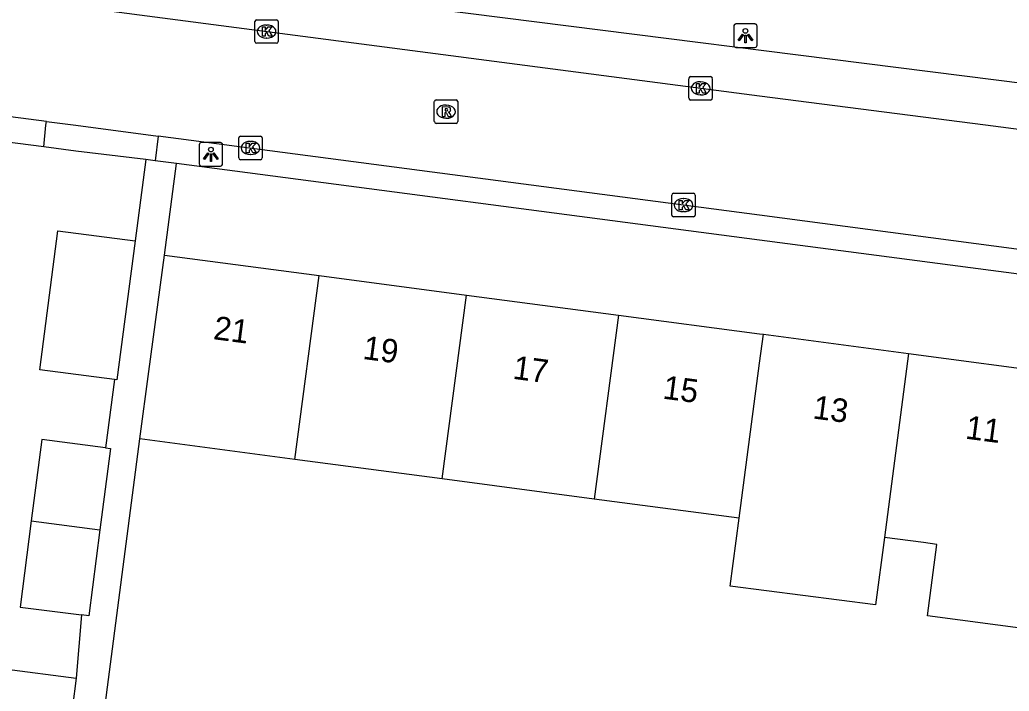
# Model space of a CAD drawing. Extents: x 162186 to 163152, y 385513 to 386513.
# Drawn here: x 162468.5 to 162510.63, y 386225.89 to 386254.5 of the extents above; entities that cross this region are included whole.
import ezdxf

# ---------------------------------------------------------------- set-up
doc = ezdxf.new("R2010")
doc.units = 0
for name, color, linetype in [('IMGEO_Kolk', 7, 'Continuous'), ('IMGEO_Lichtpunt', 7, 'Continuous'), ('IMGEO_Muur', 7, 'Continuous'), ('IMGEO_Pand', 7, 'Continuous'), ('IMGEO_Pand_nummerreeks', 7, 'Continuous'), ('IMGEO_Rijbaan_lokaal_open', 7, 'Continuous'), ('IMGEO_Rioolput', 7, 'Continuous'), ('IMGEO_Voetpad_open', 7, 'Continuous')]:
    doc.layers.add(name, color=color, linetype=linetype)

msp = doc.modelspace()

# ---------------------------------------------------------------- linework, layer by layer
at = {"layer": 'IMGEO_Kolk'}
for p, q in [((162478.506, 386253.568), (162478.506, 386254.42)), ((162478.581, 386254.494), (162479.433, 386254.494)), ((162479.507, 386254.42), (162479.507, 386253.568)), ((162478.994, 386254.274), (162479.019, 386254.274)), ((162479.433, 386253.494), (162478.581, 386253.494)), ((162479.017, 386253.714), (162478.992, 386253.714)), ((162496.989, 386251.15), (162496.989, 386252.002)), ((162497.064, 386252.076), (162497.916, 386252.076)), ((162497.477, 386251.856), (162497.502, 386251.856)), ((162497.99, 386252.002), (162497.99, 386251.15)), ((162497.916, 386251.076), (162497.064, 386251.076)), ((162497.5, 386251.296), (162497.475, 386251.296)), ((162477.822, 386248.609), (162477.822, 386249.461)), ((162477.897, 386249.535), (162478.749, 386249.535)), ((162478.31, 386249.315), (162478.335, 386249.315)), ((162478.823, 386249.461), (162478.823, 386248.609)), ((162478.749, 386248.535), (162477.897, 386248.535)), ((162478.333, 386248.755), (162478.308, 386248.755)), ((162496.263, 386246.177), (162496.263, 386247.029)), ((162496.338, 386247.103), (162497.19, 386247.103)), ((162496.751, 386246.883), (162496.776, 386246.883)), ((162497.264, 386247.029), (162497.264, 386246.177)), ((162496.774, 386246.323), (162496.749, 386246.323)), ((162497.19, 386246.103), (162496.338, 386246.103))]:
    msp.add_line(p, q, dxfattribs=at)
for points in [[(162478.506, 386253.568), (162478.506, 386254.42)], [(162478.581, 386254.494), (162479.433, 386254.494)], [(162479.507, 386254.42), (162479.507, 386253.568)], [(162478.827, 386254.194), (162478.95, 386254.194), (162478.95, 386254.043), (162479.08, 386254.194), (162479.244, 386254.194), (162479.098, 386254.043), (162479.251, 386253.794), (162479.099, 386253.794), (162479.014, 386253.958), (162478.95, 386253.891), (162478.95, 386253.794), (162478.827, 386253.794), (162478.827, 386254.194)], [(162479.433, 386253.494), (162478.581, 386253.494)], [(162496.989, 386251.15), (162496.989, 386252.002)], [(162497.064, 386252.076), (162497.916, 386252.076)], [(162497.99, 386252.002), (162497.99, 386251.15)], [(162497.31, 386251.776), (162497.433, 386251.776), (162497.433, 386251.625), (162497.563, 386251.776), (162497.727, 386251.776), (162497.581, 386251.625), (162497.734, 386251.376), (162497.582, 386251.376), (162497.497, 386251.54), (162497.433, 386251.473), (162497.433, 386251.376), (162497.31, 386251.376), (162497.31, 386251.776)], [(162497.916, 386251.076), (162497.064, 386251.076)], [(162477.822, 386248.609), (162477.822, 386249.461)], [(162477.897, 386249.535), (162478.749, 386249.535)], [(162478.823, 386249.461), (162478.823, 386248.609)], [(162478.143, 386249.235), (162478.266, 386249.235), (162478.266, 386249.084), (162478.396, 386249.235), (162478.56, 386249.235), (162478.414, 386249.084), (162478.567, 386248.835), (162478.415, 386248.835), (162478.33, 386248.999), (162478.266, 386248.932), (162478.266, 386248.835), (162478.143, 386248.835), (162478.143, 386249.235)], [(162478.749, 386248.535), (162477.897, 386248.535)], [(162496.263, 386246.177), (162496.263, 386247.029)], [(162496.338, 386247.103), (162497.19, 386247.103)], [(162496.584, 386246.803), (162496.707, 386246.803), (162496.707, 386246.652), (162496.837, 386246.803), (162497.001, 386246.803), (162496.855, 386246.652), (162497.008, 386246.403), (162496.856, 386246.403), (162496.771, 386246.567), (162496.707, 386246.5), (162496.707, 386246.403), (162496.584, 386246.403), (162496.584, 386246.803)], [(162497.264, 386247.029), (162497.264, 386246.177)], [(162497.19, 386246.103), (162496.338, 386246.103)]]:
    msp.add_lwpolyline(points, dxfattribs=at)
for centre, start, end in [((162478.583, 386254.418), 91.552, 178.448), ((162478.583, 386254.418), 91.552, 178.448), ((162479.431, 386254.418), 1.552, 88.448), ((162479.431, 386254.418), 1.552, 88.448), ((162478.583, 386253.57), 181.552, 268.448), ((162478.583, 386253.57), 181.552, 268.448), ((162479.431, 386253.57), 271.552, 358.448), ((162479.431, 386253.57), 271.552, 358.448), ((162497.066, 386252), 91.552, 178.448), ((162497.066, 386252), 91.552, 178.448), ((162497.914, 386252), 1.552, 88.448), ((162497.914, 386252), 1.552, 88.448), ((162497.066, 386251.152), 181.552, 268.448), ((162497.066, 386251.152), 181.552, 268.448), ((162497.914, 386251.152), 271.552, 358.448), ((162497.914, 386251.152), 271.552, 358.448), ((162477.899, 386249.459), 91.552, 178.448), ((162477.899, 386249.459), 91.552, 178.448), ((162478.747, 386249.459), 1.552, 88.448), ((162478.747, 386249.459), 1.552, 88.448), ((162477.899, 386248.611), 181.552, 268.448), ((162477.899, 386248.611), 181.552, 268.448), ((162478.747, 386248.611), 271.552, 358.448), ((162478.747, 386248.611), 271.552, 358.448), ((162496.34, 386247.027), 91.552, 178.448), ((162496.34, 386247.027), 91.552, 178.448), ((162497.188, 386247.027), 1.552, 88.448), ((162497.188, 386247.027), 1.552, 88.448), ((162496.34, 386246.179), 181.552, 268.448), ((162496.34, 386246.179), 181.552, 268.448), ((162497.188, 386246.179), 271.552, 358.448), ((162497.188, 386246.179), 271.552, 358.448)]:
    msp.add_arc(centre, 0.0765, start, end, dxfattribs=at)
for centre, major_axis, ratio, start_param, end_param in [((162478.993, 386253.994), (-0.387, 0.002), 0.722429, 4.712389, 7.853982), ((162479.018, 386253.994), (-0.39, 0.002), 0.717154, 1.570796, 4.712389), ((162497.476, 386251.576), (-0.387, 0.002), 0.722429, 4.712389, 7.853982), ((162497.501, 386251.576), (-0.39, 0.002), 0.717154, 1.570796, 4.712389), ((162478.309, 386249.035), (-0.387, 0.002), 0.722429, 4.712389, 7.853982), ((162478.334, 386249.035), (-0.39, 0.002), 0.717154, 1.570796, 4.712389), ((162496.75, 386246.603), (-0.387, 0.002), 0.722429, 4.712389, 7.853982), ((162496.775, 386246.603), (-0.39, 0.002), 0.717154, 1.570796, 4.712389)]:
    msp.add_ellipse(centre, major_axis=major_axis, ratio=ratio, start_param=start_param, end_param=end_param, dxfattribs=at)
at = {"layer": 'IMGEO_Lichtpunt'}
for p, q in [((162499.803, 386254.317), (162498.995, 386254.317)), ((162499.803, 386254.317), (162498.995, 386254.317)), ((162498.901, 386254.222), (162498.901, 386253.415)), ((162498.901, 386254.222), (162498.901, 386253.415)), ((162499.897, 386253.415), (162499.897, 386254.222)), ((162499.897, 386253.415), (162499.897, 386254.222)), ((162498.995, 386253.321), (162499.803, 386253.321)), ((162498.995, 386253.321), (162499.803, 386253.321)), ((162477.04, 386249.263), (162476.232, 386249.263)), ((162477.04, 386249.263), (162476.232, 386249.263)), ((162476.138, 386249.168), (162476.138, 386248.361)), ((162476.138, 386249.168), (162476.138, 386248.361)), ((162477.134, 386248.361), (162477.134, 386249.168)), ((162477.134, 386248.361), (162477.134, 386249.168)), ((162476.232, 386248.267), (162477.04, 386248.267)), ((162476.232, 386248.267), (162477.04, 386248.267))]:
    msp.add_line(p, q, dxfattribs=at)
for points in [[(162499.275, 386253.886), (162499.314, 386253.858), (162499.126, 386253.596), (162499.088, 386253.623), (162499.275, 386253.886)], [(162499.377, 386253.838), (162499.424, 386253.838), (162499.424, 386253.516), (162499.377, 386253.516), (162499.377, 386253.838)], [(162499.487, 386253.858), (162499.525, 386253.885), (162499.712, 386253.623), (162499.673, 386253.595), (162499.487, 386253.858)], [(162476.512, 386248.832), (162476.551, 386248.804), (162476.363, 386248.542), (162476.325, 386248.569), (162476.512, 386248.832)], [(162476.614, 386248.784), (162476.661, 386248.784), (162476.661, 386248.462), (162476.614, 386248.462), (162476.614, 386248.784)], [(162476.724, 386248.804), (162476.762, 386248.831), (162476.949, 386248.569), (162476.91, 386248.541), (162476.724, 386248.804)]]:
    msp.add_lwpolyline(points, dxfattribs=at)
for centre in [(162499.4, 386254.02), (162476.637, 386248.966)]:
    msp.add_circle(centre, 0.0994, dxfattribs=at)
for centre, start, end in [((162498.995, 386254.222), 90, 180), ((162498.995, 386254.222), 90, 180), ((162499.803, 386254.222), 0, 90), ((162499.803, 386254.222), 0, 90), ((162498.995, 386253.415), 180, 270), ((162498.995, 386253.415), 180, 270), ((162499.803, 386253.415), 270, 0), ((162499.803, 386253.415), 270, 360), ((162476.232, 386249.168), 90, 180), ((162476.232, 386249.168), 90, 180), ((162477.04, 386249.168), 0, 90), ((162477.04, 386249.168), 0, 90), ((162476.232, 386248.361), 180, 270), ((162476.232, 386248.361), 180, 270), ((162477.04, 386248.361), 270, 0), ((162477.04, 386248.361), 270, 360)]:
    msp.add_arc(centre, 0.0946, start, end, dxfattribs=at)
at = {"layer": 'IMGEO_Muur'}
for points in [[(162469.514, 386249.081), (162461.98, 386250.051)], [(162470.889, 386248.904), (162469.514, 386249.081)]]:
    msp.add_lwpolyline(points, dxfattribs=at)
at = {"layer": 'IMGEO_Pand'}
for points in [[(162472.525, 386239.165), (162469.346, 386239.581), (162470.121, 386245.509), (162473.41, 386245.079)], [(162473.41, 386245.079), (162472.634, 386239.151), (162472.525, 386239.165)], [(162473.616, 386236.638), (162473.997, 386239.517), (162474.653, 386244.473)], [(162474.653, 386244.473), (162481.251, 386243.6)], [(162480.216, 386235.765), (162481.251, 386243.6)], [(162481.251, 386243.6), (162487.521, 386242.77)], [(162486.486, 386234.935), (162487.521, 386242.77)], [(162487.521, 386242.77), (162493.994, 386241.914)], [(162493.994, 386241.914), (162492.958, 386234.079)], [(162493.994, 386241.914), (162500, 386241.119), (162500.162, 386241.098)], [(162499.127, 386233.263), (162500, 386239.871), (162500.162, 386241.098)], [(162500.162, 386241.098), (162506.338, 386240.28)], [(162506.338, 386240.28), (162512.974, 386239.402), (162511.938, 386231.567), (162511.535, 386228.516), (162507.152, 386229.096), (162507.555, 386232.147), (162506.982, 386232.223), (162505.316, 386232.444)], [(162506.338, 386240.28), (162505.316, 386232.444)], [(162480.216, 386235.765), (162473.616, 386236.638)], [(162472.145, 386236.261), (162469.431, 386236.611), (162468.985, 386233.151)], [(162472.145, 386236.261), (162472.358, 386236.234), (162471.911, 386232.772)], [(162486.486, 386234.935), (162480.216, 386235.765)], [(162492.958, 386234.079), (162486.486, 386234.935)], [(162499.127, 386233.263), (162492.958, 386234.079)], [(162505.316, 386232.444), (162504.936, 386229.573), (162498.744, 386230.366), (162499.127, 386233.263)], [(162468.985, 386233.151), (162468.511, 386229.478), (162471.125, 386229.14)], [(162468.985, 386233.151), (162471.911, 386232.772)], [(162471.911, 386232.772), (162471.438, 386229.1), (162471.125, 386229.14)], [(162461.727, 386227.637), (162470.903, 386226.449)], [(162470.903, 386226.449), (162470.27, 386221.555)]]:
    msp.add_lwpolyline(points, dxfattribs=at)
at = {"layer": 'IMGEO_Rijbaan_lokaal_open'}
for points in [[(162516.358, 386249.125), (162509.618, 386250), (162500, 386251.249), (162452.282, 386257.493)], [(162469.628, 386250.163), (162454.074, 386252.18), (162454.061, 386252.182), (162453.923, 386252.207), (162453.788, 386252.244), (162453.658, 386252.293), (162453.532, 386252.353), (162453.412, 386252.425), (162453.299, 386252.507), (162453.193, 386252.598), (162453.096, 386252.699), (162453.009, 386252.808), (162452.379, 386253.664), (162452.243, 386253.832), (162452.093, 386253.987), (162451.929, 386254.128), (162451.754, 386254.253), (162451.568, 386254.363), (162451.373, 386254.456), (162451.262, 386254.499)], [(162469.628, 386250.163), (162470.885, 386250), (162474.386, 386249.54)], [(162515.557, 386244.109), (162500, 386246.174), (162474.386, 386249.54)]]:
    msp.add_lwpolyline(points, dxfattribs=at)
at = {"layer": 'IMGEO_Rioolput'}
for p, q in [((162486.151, 386250.156), (162486.151, 386251.008)), ((162486.226, 386251.082), (162487.078, 386251.082)), ((162487.152, 386251.008), (162487.152, 386250.156)), ((162486.639, 386250.862), (162486.664, 386250.862)), ((162486.662, 386250.302), (162486.637, 386250.302)), ((162487.078, 386250.082), (162486.226, 386250.082))]:
    msp.add_line(p, q, dxfattribs=at)
for points in [[(162486.151, 386250.156), (162486.151, 386251.008)], [(162486.226, 386251.082), (162487.078, 386251.082)], [(162487.152, 386251.008), (162487.152, 386250.156)], [(162486.74, 386250.78), (162486.488, 386250.782), (162486.488, 386250.382)], [(162486.488, 386250.382), (162486.612, 386250.382), (162486.612, 386250.544), (162486.623, 386250.544)], [(162486.666, 386250.701), (162486.612, 386250.701), (162486.612, 386250.62)], [(162486.612, 386250.62), (162486.664, 386250.62)], [(162486.67, 386250.515), (162486.741, 386250.382), (162486.881, 386250.382), (162486.816, 386250.508)], [(162487.078, 386250.082), (162486.226, 386250.082)]]:
    msp.add_lwpolyline(points, dxfattribs=at)
for centre, radius, start, end in [((162486.228, 386251.006), 0.0765, 91.552, 178.448), ((162486.228, 386251.006), 0.0765, 91.552, 178.448), ((162487.076, 386251.006), 0.0765, 1.552, 88.448), ((162487.076, 386251.006), 0.0765, 1.552, 88.448), ((162486.622, 386250.491), 0.0533, 26.0293, 88.6989), ((162486.648, 386250.809), 0.19, 274.7715, 282.9687), ((162486.672, 386250.605), 0.0964, 77.0061, 93.1865), ((162486.686, 386250.662), 0.0378, 276.6634, 79.6772), ((162486.739, 386250.67), 0.109, 350.3612, 89.416), ((162486.737, 386250.67), 0.112, 277.5842, 350.9817), ((162486.721, 386250.455), 0.108, 29.5134, 73.7905), ((162486.228, 386250.158), 0.0765, 181.552, 268.448), ((162486.228, 386250.158), 0.0765, 181.552, 268.448), ((162487.076, 386250.158), 0.0765, 271.552, 358.448), ((162487.076, 386250.158), 0.0765, 271.552, 358.448)]:
    msp.add_arc(centre, radius, start, end, dxfattribs=at)
for centre, major_axis, ratio, start_param, end_param in [((162486.638, 386250.582), (-0.387, 0.002), 0.722429, 4.712389, 7.853982), ((162486.663, 386250.582), (-0.39, 0.002), 0.717154, 1.570796, 4.712389)]:
    msp.add_ellipse(centre, major_axis=major_axis, ratio=ratio, start_param=start_param, end_param=end_param, dxfattribs=at)
at = {"layer": 'IMGEO_Voetpad_open'}
for points in [[(162477.472, 386256.096), (162482.084, 386255.488), (162514.241, 386251.416)], [(162469.514, 386249.081), (162461.98, 386250.051), (162451.89, 386251.431)], [(162469.514, 386249.081), (162469.611, 386250), (162469.628, 386250.163)], [(162474.386, 386249.54), (162474.268, 386248.494)], [(162473.863, 386248.543), (162470.889, 386248.904), (162469.514, 386249.081)], [(162473.863, 386248.543), (162473.41, 386245.079)], [(162474.268, 386248.494), (162473.863, 386248.543)], [(162475.169, 386248.376), (162474.268, 386248.494)], [(162474.653, 386244.473), (162475.169, 386248.376)], [(162514.83, 386243.164), (162500, 386245.113), (162475.169, 386248.376)], [(162472.525, 386239.165), (162472.145, 386236.261)], [(162472.041, 386224.64), (162473.616, 386236.638)], [(162471.125, 386229.14), (162470.903, 386226.449)]]:
    msp.add_lwpolyline(points, dxfattribs=at)

# ---------------------------------------------------------------- texts
at = {"layer": 'IMGEO_Pand_nummerreeks'}
for s, p in [('21', (162476.709, 386240.892)), ('19', (162483.074, 386240.05)), ('17', (162489.461, 386239.205)), ('15', (162495.847, 386238.36)), ('13', (162502.234, 386237.515)), ('11', (162508.734, 386236.655))]:
    msp.add_text(s, height=1, rotation=352.4619, dxfattribs=at).set_placement(p)

doc.saveas('drawing.dxf')
